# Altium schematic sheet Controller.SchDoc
size A; SheetNumber: 2; SheetTotal: 2
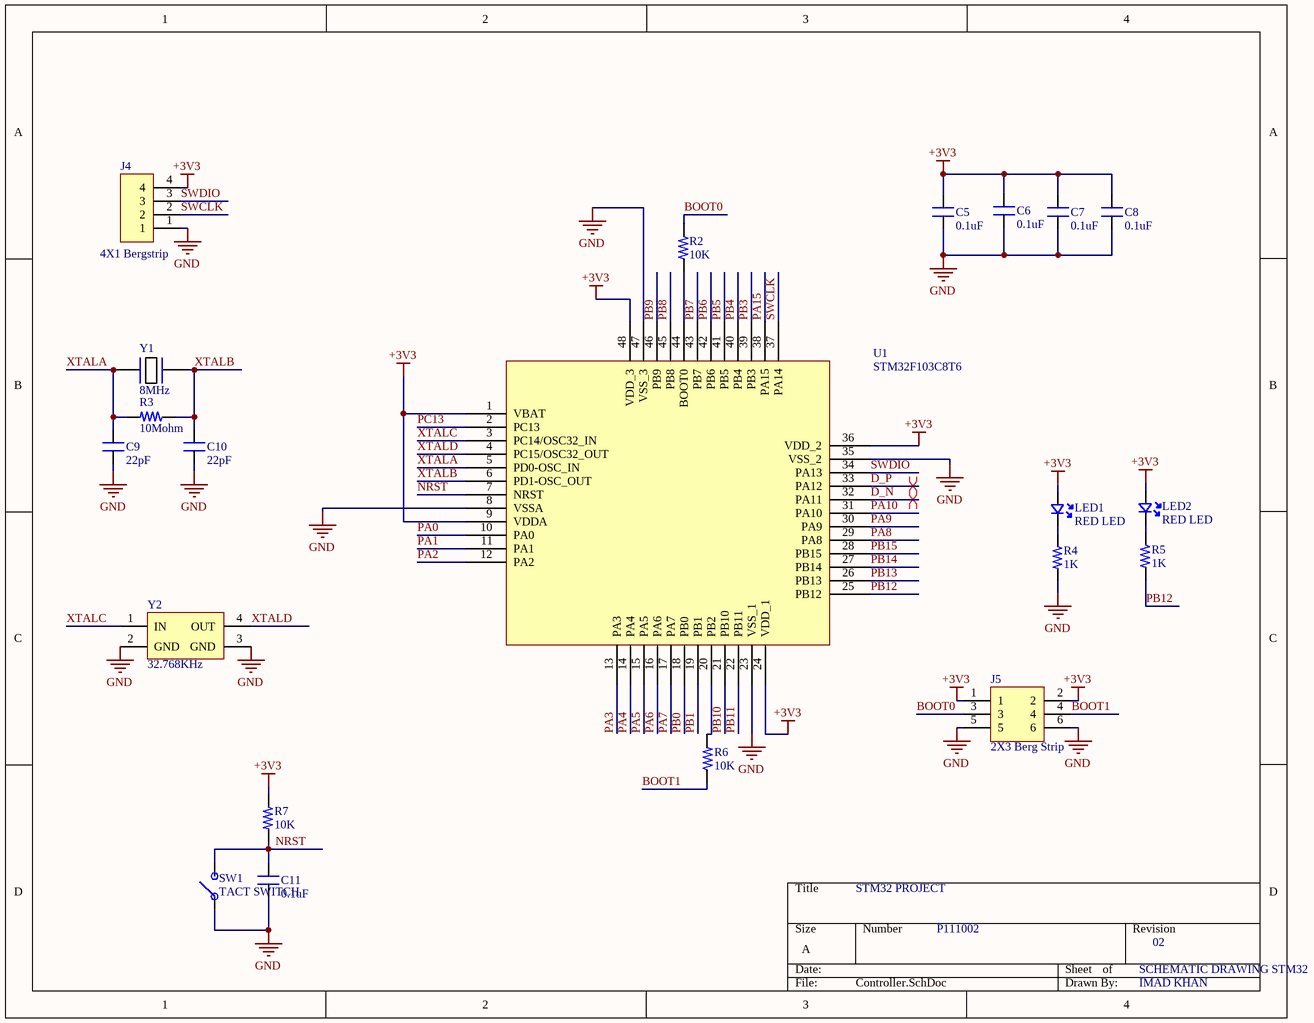
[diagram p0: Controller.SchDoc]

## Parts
C5  0.1uF  [CAP_0805]
C6  0.1uF  [CAP_0805]
C7  0.1uF  [CAP_0805]
C8  0.1uF  [CAP_0805]
C9  22pF  [CAP_0805]
C10  22pF  [CAP_0805]
C11  0.1uF  [CAP_0805]
J4  4X1 Bergstrip  [CON4_100_40D72_TH_ST_MALE]
J5  2X3 Berg Strip  [CON6_100_59D78_TH_ST_Duplicate]
LED1  RED LED  [LED_0805]
LED2  RED LED  [LED_0805]
R2  10K  [RES_0805]
R3  10Mohm  [RES_0805]
R4  1K  [RES_0805]
R5  1K  [RES_0805]
R6  10K  [RES_0805]
R7  10K  [RES_0805]
SW1  TACT SWITCH  [SW_342_SMD]
U1  STM32F103C8T6  [LQFP-48_19.6_393_58X11_SMD]
Y1  8MHz  [XTAL_314_240X47_SMD]
Y2  32.768KHz  [XTAL_MC-405 32.7680K-G3]

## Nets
+3V3: C5.2 C6.2 C7.2 C8.2 J4.4 J5.1 J5.2 LED1.A LED2.A R7.2 U1.1(VBAT) U1.9(VDDA) U1.24(VDD_1) U1.36(VDD_2) U1.48(VDD_3)
GND: C5.1 C6.1 C7.1 C8.1 C9.1 C10.1 C11.1 J4.1 J5.5 J5.6 R4.1 SW1.1 U1.8(VSSA) U1.23(VSS_1) U1.35(VSS_2) U1.47(VSS_3) Y2.2(GND) Y2.3(GND)
BOOT0: J5.3 R2.2
BOOT1: J5.4 R6.2
D_N: U1.32(PA11)
D_P: U1.33(PA12)
NRST: C11.2 R7.1 SW1.2 U1.7(NRST)
PA0: U1.10(PA0)
PA1: U1.11(PA1)
PA2: U1.12(PA2)
PA3: U1.13(PA3)
PA4: U1.14(PA4)
PA5: U1.15(PA5)
PA6: U1.16(PA6)
PA7: U1.17(PA7)
PA8: U1.29(PA8)
PA9: U1.30(PA9)
PA10: U1.31(PA10)
PA15: U1.38(PA15)
PB0: U1.18(PB0)
PB1: U1.19(PB1)
PB3: U1.39(PB3)
PB4: U1.40(PB4)
PB5: U1.41(PB5)
PB6: U1.42(PB6)
PB7: U1.43(PB7)
PB8: U1.45(PB8)
PB9: U1.46(PB9)
PB10: U1.21(PB10)
PB11: U1.22(PB11)
PB12: R5.1 U1.25(PB12)
PB13: U1.26(PB13)
PB14: U1.27(PB14)
PB15: U1.28(PB15)
PC13: U1.2(PC13)
SWCLK: J4.2 U1.37(PA14)
SWDIO: J4.3 U1.34(PA13)
XTALA: C9.2 R3.1 U1.5(PD0-OSC_IN) Y1.1
XTALB: C10.2 R3.2 U1.6(PD1-OSC_OUT) Y1.2
XTALC: U1.3(PC14/OSC32_IN) Y2.1(IN)
XTALD: U1.4(PC15/OSC32_OUT) Y2.4(OUT)
NetLED1_K: LED1.K R4.2
NetLED2_K: LED2.K R5.2
NetR2_1: R2.1 U1.44(BOOT0)
NetR6_1: R6.1 U1.20(PB2)

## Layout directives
differential pair; differential pair class diff_90: D_N, D_P

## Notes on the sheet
- STM32 PROJECT
- P111002
- SCHEMATIC DRAWING STM32
- 02
- IMAD KHAN

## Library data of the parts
C5-C8 C11 = CAP_0.1uF-50V-5%-0805: 0.1µF ±5% 50V Ceramic Capacitor X7R 0805 (2012 Metric); Manufacturer: KEMET; Manufacturing Part Number: C0805C104J5RACTU
C9 C10 = CAP_22pF-50V-5%-0805: 22pF ±5% 50V Ceramic Capacitor C0G, NP0 0805 (2012 Metric); Manufacturer: KEMET; Manufacturer Part Number: C0805C220J5GACTU
J4 = CON-BS-PLG_4X1-100-TH-ST: 4 pin, 1 row, 2.54mm pitch bergstrip; Manufacturer: NA
J5 = CON-BS-PLG_2X3-100-TH-ST: 6 pin, 2 row, 2.54mm pitch bergstrip; Manufacturer: NA
LED1 LED2 = LED-RED_10mA-0805: Red 621nm LED Indication - Discrete 2V 0805 (2012 Metric); Manufacturer: Lite-On Inc.; Manufacturer Part Number: LTST-C170EKT
R2 R6 R7 = RES_10K-0.125W-1%-0805: 10 kOhms ±1% 0.125W, 1/8W Chip Resistor 0805 (2012 Metric) Moisture Resistant Thick Film; Manufacturer: Yageo; Manufacturing Part Number: RC0805FR-0710KL
R3 = RES_10MOHM-0.125W-1%-0805: 10 MOhms ±1% 0.125W, 1/8W Chip Resistor 0805 (2012 Metric) Automotive AEC-Q200, High Voltage Thick Film; Manufacturer: Rohm Semiconductor; Manufacturing Part Number: KTR10EZPF1005
R4 R5 = RES_1K-0.125W-1%-0805: 1 kOhms ±1% 0.125W, 1/8W Chip Resistor 0805 (2012 Metric) Moisture Resistant Thick Film; Manufacturer: 垈㎵á; Manufacturer Part Number: RC0805FR-071KL
SW1 = SW_KSR223GLFG-SMD: Tactile Switch SPST-NO Top Actuated Surface Mount; Manufacturer: C&K
U1 = IC-STM32F103C8T6 _1: ARM® Cortex®-M3 STM32F1 Microcontroller IC 32-Bit 72MHz 64KB (64K x 8) FLASH; Manufacturer: STMicroelectronics
Y1 = XTAL_8MHZ-LFXTAL030234: Crystals 8MHz 22pF -20C 70C; Manufacturer: IQD Frequency Products; Manufacturing Part Number: LFXTAL030234Reel
Y2 = XTAL_32.768KHz-MC-405 32.7680K-G3: Crystals SMD AT XTL MHZ +/-50PPM 12.5 PF 250 T/R; Manufacturer: Epson; Manufacturing Part Number: MC-405 32.7680K-G3: ROHS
